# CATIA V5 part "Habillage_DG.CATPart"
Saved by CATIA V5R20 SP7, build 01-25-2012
Part number: Habillage_DG
Bounding box of the stored display mesh (mm): x -2 to 4.1, y -55 to -18.062, z -12.482 to 61.982
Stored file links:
  F:\IAO\Catia\Habillage_DG.CATPart
  F:\IAO\Catia\asandre.CATProduct
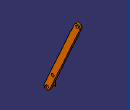
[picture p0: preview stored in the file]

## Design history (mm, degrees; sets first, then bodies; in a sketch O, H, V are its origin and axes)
Set1
  Plane1 "Plan.2,1": linked copy from another document
  Point1 "D": linked copy from another document
  Point2 "G": linked copy from another document
  Point3 "E": linked copy from another document
Body1 (main body)
  Sketch1 "Bielle_DG" on Plane1, origin (2.1, 0, 0), H (0, 1, 0), V (0, 0, 1)
    construction line L1 (-21, 59) -> (-52, -9.5)
    point P1 (-21, 59)
    point P2 (-52, -9.5)
    line L2 (-18.2669, 57.7631) -> (-49.2669, -10.7369)
    line L3 (-54.7331, -8.2631) -> (-23.7331, 60.2369)
    arc A1 centre (-52, -9.5) radius 3 from (-49.2669, -10.7369) to (-54.7331, -8.2631) cw
    arc A2 centre (-21, 59) radius 3 from (-23.7331, 60.2369) to (-18.2669, 57.7631) cw
    reference projected point E1 (-21, 59) from Point1
    reference projected point E2 (-52, -9.5) from Point2
    circle A3 centre (-52, -9.5) radius 1.5
    point P7 (-52, -9.5)
    reference projected point E3 (-52, -9.5) from Point2
    circle A4 centre (-46.0959, 3.5462) radius 1.5
    point P8 (-46.0959, 3.5462)
    reference projected point E4 (-46.0959, 3.5462) from Point3
    circle A5 centre (-21, 59) radius 1.5
    point P9 (-21, 59)
    reference projected point E5 (-21, 59) from Point1
    distance L1 L2 = 3
    radius A3 = 1.5
    radius A4 = 1.5
    radius A5 = 1.5
    tangency: A1 L2, A2 L2, A1 L3, A2 L3
    coincidence: P1 E1, P2 E2, P7 E3, P8 E4, P9 E5
  Pad1 "Bielle_DG": profile Sketch1, direction (1, 0, 0), length 2
  Sketch2 "Lien.Plan.-2.et.plan.2.1" on Plane1, origin (2.1, 0, 0), H (0, 1, 0), V (0, 0, 1)
    circle A1 centre (-52, -9.5) radius 3
    point P1 (-52, -9.5)
    reference projected point E1 (-52, -9.5) from Point2
    circle A2 centre (-52, -9.5) radius 1.5
    point P2 (-52, -9.5)
    reference projected point E2 (-52, -9.5) from Point2
    radius A1 = 3
    radius A2 = 1.5
    coincidence: P1 E1, P2 E2
  Pad2 "Lien.Plan.-2.et.2.1": profile Sketch2, direction (-1, 0, 0), length 4.1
